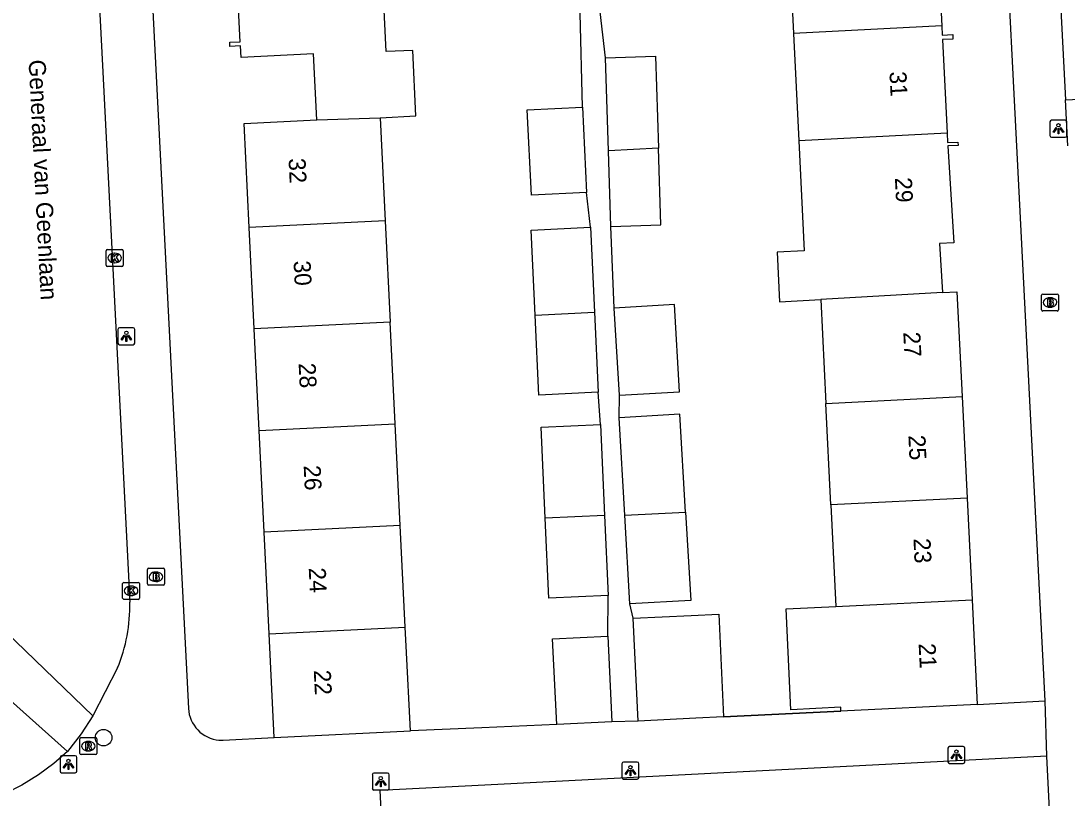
# Model space of a CAD drawing. Extents: x 161084 to 161928, y 385355 to 386522.
# Drawn here: x 161408.5 to 161470.2, y 385913.5 to 385959.4 of the extents above; entities that cross this region are included whole.
import ezdxf

# ---------------------------------------------------------------- set-up
doc = ezdxf.new("R2010")
doc.units = 0
for name, color, linetype in [('IMGEO_Boom', 7, 'Continuous'), ('IMGEO_Brandkraan', 7, 'Continuous'), ('IMGEO_Kolk', 7, 'Continuous'), ('IMGEO_Lichtpunt', 7, 'Continuous'), ('IMGEO_Muur', 7, 'Continuous'), ('IMGEO_Openbare_ruimte_label', 7, 'Continuous'), ('IMGEO_Pand', 7, 'Continuous'), ('IMGEO_Pand_nummerreeks', 7, 'Continuous'), ('IMGEO_Rijbaan_lokaal_open', 7, 'Continuous'), ('IMGEO_Rioolput', 7, 'Continuous'), ('IMGEO_Voetpad_open', 7, 'Continuous')]:
    doc.layers.add(name, color=color, linetype=linetype)

msp = doc.modelspace()

# ---------------------------------------------------------------- linework, layer by layer
at = {"layer": 'IMGEO_Boom'}
msp.add_circle((161413.361, 385917.085), 0.489, dxfattribs=at)
at = {"layer": 'IMGEO_Brandkraan'}
for p, q in [((161468.709, 385942.329), (161468.709, 385943.181)), ((161468.784, 385943.255), (161469.636, 385943.255)), ((161469.71, 385943.181), (161469.71, 385942.329)), ((161469.197, 385943.035), (161469.222, 385943.035)), ((161469.636, 385942.255), (161468.784, 385942.255)), ((161469.22, 385942.475), (161469.195, 385942.475)), ((161416.024, 385927.077), (161416.876, 385927.077)), ((161415.949, 385926.151), (161415.949, 385927.003)), ((161416.437, 385926.857), (161416.462, 385926.857)), ((161416.95, 385927.003), (161416.95, 385926.151)), ((161416.876, 385926.077), (161416.024, 385926.077)), ((161416.46, 385926.297), (161416.435, 385926.297))]:
    msp.add_line(p, q, dxfattribs=at)
for points in [[(161468.709, 385942.329), (161468.709, 385943.181)], [(161468.784, 385943.255), (161469.636, 385943.255)], [(161469.71, 385943.181), (161469.71, 385942.329)], [(161469.057, 385942.955), (161469.057, 385942.555), (161469.27, 385942.555)], [(161469.288, 385942.955), (161469.057, 385942.955)], [(161469.236, 385942.874), (161469.182, 385942.874), (161469.182, 385942.798)], [(161469.182, 385942.798), (161469.235, 385942.798)], [(161469.244, 385942.722), (161469.182, 385942.722), (161469.182, 385942.641)], [(161469.182, 385942.641), (161469.244, 385942.641)], [(161469.636, 385942.255), (161468.784, 385942.255)], [(161416.024, 385927.077), (161416.876, 385927.077)], [(161415.949, 385926.151), (161415.949, 385927.003)], [(161416.297, 385926.777), (161416.297, 385926.377), (161416.51, 385926.377)], [(161416.528, 385926.777), (161416.297, 385926.777)], [(161416.476, 385926.696), (161416.422, 385926.696), (161416.422, 385926.62)], [(161416.422, 385926.62), (161416.475, 385926.62)], [(161416.484, 385926.544), (161416.422, 385926.544), (161416.422, 385926.463)], [(161416.422, 385926.463), (161416.484, 385926.463)], [(161416.95, 385927.003), (161416.95, 385926.151)], [(161416.876, 385926.077), (161416.024, 385926.077)]]:
    msp.add_lwpolyline(points, dxfattribs=at)
for centre, radius, start, end in [((161468.786, 385943.179), 0.0765, 91.55205, 178.44795), ((161468.786, 385943.179), 0.0765, 91.55205, 178.44795), ((161469.634, 385943.179), 0.0765, 1.55205, 88.44795), ((161469.634, 385943.179), 0.0765, 1.55205, 88.44795), ((161469.237, 385942.836), 0.0379, 267.82845, 90.93552), ((161469.245, 385942.681), 0.0404, 269.87594, 90.50774), ((161469.276, 385942.806), 0.251, 268.66757, 293.53466), ((161469.292, 385942.81), 0.145, 59.4692, 91.53667), ((161469.317, 385942.857), 0.0922, 285.51372, 58.15012), ((161469.322, 385942.665), 0.105, 301.31148, 78.98903), ((161468.786, 385942.331), 0.0765, 181.55205, 268.44795), ((161468.786, 385942.331), 0.0765, 181.55205, 268.44795), ((161469.634, 385942.331), 0.0765, 271.55205, 358.44795), ((161469.634, 385942.331), 0.0765, 271.55205, 358.44795), ((161416.026, 385927.001), 0.0765, 91.55205, 178.44795), ((161416.026, 385927.001), 0.0765, 91.55205, 178.44795), ((161416.874, 385927.001), 0.0765, 1.55205, 88.44795), ((161416.874, 385927.001), 0.0765, 1.55205, 88.44795), ((161416.477, 385926.658), 0.0379, 267.82845, 90.93552), ((161416.485, 385926.503), 0.0404, 269.87594, 90.50774), ((161416.532, 385926.632), 0.145, 59.4692, 91.53667), ((161416.557, 385926.679), 0.0922, 285.51372, 58.15012), ((161416.562, 385926.487), 0.105, 301.31148, 78.98903), ((161416.026, 385926.153), 0.0765, 181.55205, 268.44795), ((161416.026, 385926.153), 0.0765, 181.55205, 268.44795), ((161416.516, 385926.628), 0.251, 268.66757, 293.53466), ((161416.874, 385926.153), 0.0765, 271.55205, 358.44795), ((161416.874, 385926.153), 0.0765, 271.55205, 358.44795)]:
    msp.add_arc(centre, radius, start, end, dxfattribs=at)
for centre, major_axis, ratio, start_param, end_param in [((161469.196, 385942.755), (-0.387, 0.002), 0.722429, 4.712389, 7.853982), ((161469.221, 385942.755), (-0.39, 0.002), 0.717154, 1.570796, 4.712389), ((161416.436, 385926.577), (-0.387, 0.002), 0.722429, 4.712389, 7.853982), ((161416.461, 385926.577), (-0.39, 0.002), 0.717154, 1.570796, 4.712389)]:
    msp.add_ellipse(centre, major_axis=major_axis, ratio=ratio, start_param=start_param, end_param=end_param, dxfattribs=at)
at = {"layer": 'IMGEO_Kolk'}
for p, q in [((161413.518, 385944.958), (161413.518, 385945.81)), ((161413.593, 385945.884), (161414.445, 385945.884)), ((161414.006, 385945.664), (161414.031, 385945.664)), ((161414.519, 385945.81), (161414.519, 385944.958)), ((161414.029, 385945.104), (161414.004, 385945.104)), ((161414.445, 385944.884), (161413.593, 385944.884)), ((161414.486, 385925.319), (161414.486, 385926.171)), ((161414.561, 385926.245), (161415.413, 385926.245)), ((161414.974, 385926.025), (161414.999, 385926.025)), ((161415.487, 385926.171), (161415.487, 385925.319)), ((161415.413, 385925.245), (161414.561, 385925.245)), ((161414.997, 385925.465), (161414.972, 385925.465))]:
    msp.add_line(p, q, dxfattribs=at)
for points in [[(161413.518, 385944.958), (161413.518, 385945.81)], [(161413.593, 385945.884), (161414.445, 385945.884)], [(161414.519, 385945.81), (161414.519, 385944.958)], [(161413.839, 385945.584), (161413.962, 385945.584), (161413.962, 385945.433), (161414.092, 385945.584), (161414.256, 385945.584), (161414.11, 385945.433), (161414.263, 385945.184), (161414.111, 385945.184), (161414.026, 385945.348), (161413.962, 385945.281), (161413.962, 385945.184), (161413.839, 385945.184), (161413.839, 385945.584)], [(161414.445, 385944.884), (161413.593, 385944.884)], [(161414.486, 385925.319), (161414.486, 385926.171)], [(161414.561, 385926.245), (161415.413, 385926.245)], [(161414.807, 385925.945), (161414.93, 385925.945), (161414.93, 385925.794), (161415.06, 385925.945), (161415.224, 385925.945), (161415.078, 385925.794), (161415.231, 385925.545), (161415.079, 385925.545), (161414.994, 385925.709), (161414.93, 385925.642), (161414.93, 385925.545), (161414.807, 385925.545), (161414.807, 385925.945)], [(161415.487, 385926.171), (161415.487, 385925.319)], [(161415.413, 385925.245), (161414.561, 385925.245)]]:
    msp.add_lwpolyline(points, dxfattribs=at)
for centre, start, end in [((161413.595, 385945.808), 91.55205, 178.44795), ((161413.595, 385945.808), 91.55205, 178.44795), ((161414.443, 385945.808), 1.55205, 88.44795), ((161414.443, 385945.808), 1.55205, 88.44795), ((161413.595, 385944.96), 181.55205, 268.44795), ((161413.595, 385944.96), 181.55205, 268.44795), ((161414.443, 385944.96), 271.55205, 358.44795), ((161414.443, 385944.96), 271.55205, 358.44795), ((161414.563, 385926.169), 91.55205, 178.44795), ((161414.563, 385926.169), 91.55205, 178.44795), ((161415.411, 385926.169), 1.55205, 88.44795), ((161415.411, 385926.169), 1.55205, 88.44795), ((161414.563, 385925.321), 181.55205, 268.44795), ((161414.563, 385925.321), 181.55205, 268.44795), ((161415.411, 385925.321), 271.55205, 358.44795), ((161415.411, 385925.321), 271.55205, 358.44795)]:
    msp.add_arc(centre, 0.0765, start, end, dxfattribs=at)
for centre, major_axis, ratio, start_param, end_param in [((161414.005, 385945.384), (-0.387, 0.002), 0.722429, 4.712389, 7.853982), ((161414.03, 385945.384), (-0.39, 0.002), 0.717154, 1.570796, 4.712389), ((161414.973, 385925.745), (-0.387, 0.002), 0.722429, 4.712389, 7.853982), ((161414.998, 385925.745), (-0.39, 0.002), 0.717154, 1.570796, 4.712389)]:
    msp.add_ellipse(centre, major_axis=major_axis, ratio=ratio, start_param=start_param, end_param=end_param, dxfattribs=at)
at = {"layer": 'IMGEO_Lichtpunt'}
for p, q in [((161469.204, 385953.412), (161469.204, 385952.605)), ((161469.204, 385953.412), (161469.204, 385952.605)), ((161470.106, 385953.507), (161469.298, 385953.507)), ((161470.106, 385953.507), (161469.298, 385953.507)), ((161470.2, 385952.605), (161470.2, 385953.412)), ((161470.2, 385952.605), (161470.2, 385953.412)), ((161469.298, 385952.511), (161470.106, 385952.511)), ((161469.298, 385952.511), (161470.106, 385952.511)), ((161415.11, 385941.264), (161414.302, 385941.264)), ((161415.11, 385941.264), (161414.302, 385941.264)), ((161414.208, 385941.169), (161414.208, 385940.362)), ((161414.208, 385941.169), (161414.208, 385940.362)), ((161415.204, 385940.362), (161415.204, 385941.169)), ((161415.204, 385940.362), (161415.204, 385941.169)), ((161414.302, 385940.268), (161415.11, 385940.268)), ((161414.302, 385940.268), (161415.11, 385940.268)), ((161411.694, 385916.012), (161410.886, 385916.012)), ((161411.694, 385916.012), (161410.886, 385916.012)), ((161463.185, 385916.467), (161463.185, 385915.66)), ((161463.185, 385916.467), (161463.185, 385915.66)), ((161464.087, 385916.562), (161463.279, 385916.562)), ((161464.087, 385916.562), (161463.279, 385916.562)), ((161464.181, 385915.66), (161464.181, 385916.467)), ((161464.181, 385915.66), (161464.181, 385916.467)), ((161410.792, 385915.917), (161410.792, 385915.11)), ((161410.792, 385915.917), (161410.792, 385915.11)), ((161411.788, 385915.11), (161411.788, 385915.917)), ((161411.788, 385915.11), (161411.788, 385915.917)), ((161443.951, 385915.545), (161443.951, 385914.738)), ((161443.951, 385915.545), (161443.951, 385914.738)), ((161444.853, 385915.64), (161444.045, 385915.64)), ((161444.853, 385915.64), (161444.045, 385915.64)), ((161444.947, 385914.738), (161444.947, 385915.545)), ((161444.947, 385914.738), (161444.947, 385915.545)), ((161463.279, 385915.566), (161464.087, 385915.566)), ((161463.279, 385915.566), (161464.087, 385915.566)), ((161410.886, 385915.016), (161411.694, 385915.016)), ((161410.886, 385915.016), (161411.694, 385915.016)), ((161429.22, 385914.899), (161429.22, 385914.092)), ((161429.22, 385914.899), (161429.22, 385914.092)), ((161430.122, 385914.994), (161429.314, 385914.994)), ((161430.122, 385914.994), (161429.314, 385914.994)), ((161430.216, 385914.092), (161430.216, 385914.899)), ((161430.216, 385914.092), (161430.216, 385914.899)), ((161444.045, 385914.644), (161444.853, 385914.644)), ((161444.045, 385914.644), (161444.853, 385914.644)), ((161429.314, 385913.998), (161430.122, 385913.998)), ((161429.314, 385913.998), (161430.122, 385913.998))]:
    msp.add_line(p, q, dxfattribs=at)
for points in [[(161469.578, 385953.076), (161469.617, 385953.048), (161469.429, 385952.786), (161469.391, 385952.813), (161469.578, 385953.076)], [(161469.68, 385953.028), (161469.727, 385953.028), (161469.727, 385952.706), (161469.68, 385952.706), (161469.68, 385953.028)], [(161469.79, 385953.048), (161469.828, 385953.075), (161470.015, 385952.813), (161469.976, 385952.785), (161469.79, 385953.048)], [(161414.582, 385940.833), (161414.621, 385940.805), (161414.433, 385940.543), (161414.395, 385940.57), (161414.582, 385940.833)], [(161414.684, 385940.785), (161414.731, 385940.785), (161414.731, 385940.463), (161414.684, 385940.463), (161414.684, 385940.785)], [(161414.794, 385940.805), (161414.832, 385940.832), (161415.019, 385940.57), (161414.98, 385940.542), (161414.794, 385940.805)], [(161463.559, 385916.131), (161463.598, 385916.103), (161463.41, 385915.841), (161463.372, 385915.868), (161463.559, 385916.131)], [(161463.661, 385916.083), (161463.708, 385916.083), (161463.708, 385915.761), (161463.661, 385915.761), (161463.661, 385916.083)], [(161463.771, 385916.103), (161463.809, 385916.13), (161463.996, 385915.868), (161463.957, 385915.84), (161463.771, 385916.103)], [(161411.166, 385915.581), (161411.205, 385915.553), (161411.017, 385915.291), (161410.979, 385915.318), (161411.166, 385915.581)], [(161411.268, 385915.533), (161411.315, 385915.533), (161411.315, 385915.211), (161411.268, 385915.211), (161411.268, 385915.533)], [(161411.378, 385915.553), (161411.416, 385915.58), (161411.603, 385915.318), (161411.564, 385915.29), (161411.378, 385915.553)], [(161444.325, 385915.209), (161444.364, 385915.181), (161444.176, 385914.919), (161444.138, 385914.946), (161444.325, 385915.209)], [(161444.427, 385915.161), (161444.474, 385915.161), (161444.474, 385914.839), (161444.427, 385914.839), (161444.427, 385915.161)], [(161444.537, 385915.181), (161444.575, 385915.208), (161444.762, 385914.946), (161444.723, 385914.918), (161444.537, 385915.181)], [(161429.594, 385914.563), (161429.633, 385914.535), (161429.445, 385914.273), (161429.407, 385914.3), (161429.594, 385914.563)], [(161429.696, 385914.515), (161429.743, 385914.515), (161429.743, 385914.193), (161429.696, 385914.193), (161429.696, 385914.515)], [(161429.806, 385914.535), (161429.844, 385914.562), (161430.031, 385914.3), (161429.992, 385914.272), (161429.806, 385914.535)]]:
    msp.add_lwpolyline(points, dxfattribs=at)
for centre in [(161469.703, 385953.21), (161414.707, 385940.967), (161463.684, 385916.265), (161411.291, 385915.715), (161444.45, 385915.343), (161429.719, 385914.697)]:
    msp.add_circle(centre, 0.0994, dxfattribs=at)
for centre, start, end in [((161469.298, 385953.412), 90, 180), ((161469.298, 385953.412), 90, 180), ((161470.106, 385953.412), 0, 90), ((161470.106, 385953.412), 0, 90), ((161469.298, 385952.605), 180, 270), ((161469.298, 385952.605), 180, 270), ((161470.106, 385952.605), 270, 0), ((161470.106, 385952.605), 270, 360), ((161414.302, 385941.169), 90, 180), ((161414.302, 385941.169), 90, 180), ((161415.11, 385941.169), 0, 90), ((161415.11, 385941.169), 0, 90), ((161414.302, 385940.362), 180, 270), ((161414.302, 385940.362), 180, 270), ((161415.11, 385940.362), 270, 0), ((161415.11, 385940.362), 270, 360), ((161410.886, 385915.917), 90, 180), ((161410.886, 385915.917), 90, 180), ((161411.694, 385915.917), 0, 90), ((161411.694, 385915.917), 0, 90), ((161463.279, 385916.467), 90, 180), ((161463.279, 385916.467), 90, 180), ((161464.087, 385916.467), 0, 90), ((161464.087, 385916.467), 0, 90), ((161444.045, 385915.545), 90, 180), ((161444.045, 385915.545), 90, 180), ((161444.853, 385915.545), 0, 90), ((161444.853, 385915.545), 0, 90), ((161463.279, 385915.66), 180, 270), ((161463.279, 385915.66), 180, 270), ((161464.087, 385915.66), 270, 0), ((161464.087, 385915.66), 270, 360), ((161410.886, 385915.11), 180, 270), ((161410.886, 385915.11), 180, 270), ((161411.694, 385915.11), 270, 0), ((161411.694, 385915.11), 270, 360), ((161429.314, 385914.899), 90, 180), ((161429.314, 385914.899), 90, 180), ((161430.122, 385914.899), 0, 90), ((161430.122, 385914.899), 0, 90), ((161444.045, 385914.738), 180, 270), ((161444.045, 385914.738), 180, 270), ((161444.853, 385914.738), 270, 0), ((161444.853, 385914.738), 270, 360), ((161429.314, 385914.092), 180, 270), ((161429.314, 385914.092), 180, 270), ((161430.122, 385914.092), 270, 0), ((161430.122, 385914.092), 270, 360)]:
    msp.add_arc(centre, 0.0946, start, end, dxfattribs=at)
at = {"layer": 'IMGEO_Muur'}
for points in [[(161449.948, 385918.309), (161456.873, 385918.643)], [(161440.097, 385917.865), (161435.675, 385917.671)], [(161435.675, 385917.671), (161431.468, 385917.486)]]:
    msp.add_lwpolyline(points, dxfattribs=at)
at = {"layer": 'IMGEO_Pand'}
for points in [[(161462.514, 385965.409), (161462.544, 385964.801), (161463.153, 385964.831), (161463.165, 385964.591), (161462.547, 385964.56), (161462.817, 385959.075)], [(161453.757, 385964.955), (161454.069, 385958.622)], [(161425.937, 385953.528), (161425.745, 385957.419), (161421.473, 385957.208), (161421.439, 385957.896), (161420.816, 385957.865), (161420.804, 385958.11), (161421.415, 385958.14), (161421.144, 385963.626)], [(161429.681, 385953.656), (161431.792, 385953.761), (161431.601, 385957.62), (161430.045, 385957.571), (161429.724, 385964.062)], [(161462.817, 385959.075), (161454.069, 385958.622)], [(161454.069, 385958.622), (161454.38, 385952.29)], [(161462.817, 385959.075), (161462.844, 385958.532), (161463.467, 385958.563), (161463.48, 385958.299), (161462.861, 385958.269), (161463.133, 385952.744)], [(161442.975, 385957.188), (161445.932, 385957.281), (161446.103, 385951.861)], [(161443.148, 385951.707), (161442.975, 385957.188)], [(161441.86, 385949.243), (161438.602, 385949.087), (161438.361, 385954.131), (161441.619, 385954.287)], [(161441.619, 385954.287), (161441.86, 385949.243)], [(161425.937, 385953.528), (161429.681, 385953.656)], [(161429.681, 385953.656), (161429.981, 385947.583)], [(161421.951, 385947.187), (161421.648, 385953.316), (161425.937, 385953.528)], [(161463.133, 385952.744), (161454.38, 385952.29)], [(161463.133, 385952.744), (161463.16, 385952.19), (161463.772, 385952.22), (161463.782, 385952.019), (161463.18, 385951.989), (161463.536, 385946.272), (161462.687, 385946.227), (161462.857, 385943.338)], [(161446.103, 385951.861), (161443.148, 385951.707)], [(161443.289, 385947.244), (161446.246, 385947.338), (161446.103, 385951.861)], [(161454.38, 385952.29), (161454.699, 385945.795), (161453.112, 385945.717), (161453.236, 385942.788), (161455.678, 385942.939)], [(161443.289, 385947.244), (161443.148, 385951.707)], [(161429.981, 385947.583), (161421.951, 385947.187)], [(161429.981, 385947.583), (161430.277, 385941.59)], [(161422.247, 385941.194), (161421.951, 385947.187)], [(161438.83, 385942.012), (161438.597, 385947.031), (161442.097, 385947.193)], [(161442.097, 385947.193), (161442.33, 385942.184)], [(161462.857, 385943.338), (161455.678, 385942.939)], [(161462.857, 385943.338), (161463.716, 385943.38), (161464.02, 385937.202)], [(161443.795, 385937.285), (161447.353, 385937.493), (161447.053, 385942.629), (161443.495, 385942.422)], [(161455.678, 385942.939), (161455.98, 385936.805)], [(161438.83, 385942.012), (161442.33, 385942.184)], [(161442.549, 385937.46), (161439.049, 385937.297), (161438.83, 385942.012)], [(161442.33, 385942.184), (161442.549, 385937.46)], [(161443.795, 385937.285), (161443.495, 385942.422)], [(161430.277, 385941.59), (161422.247, 385941.194)], [(161430.573, 385935.598), (161430.277, 385941.59)], [(161422.543, 385935.202), (161422.247, 385941.194)], [(161455.98, 385936.805), (161464.02, 385937.202)], [(161464.02, 385937.202), (161464.314, 385931.21)], [(161456.275, 385930.814), (161455.98, 385936.805)], [(161447.707, 385930.392), (161447.372, 385936.166), (161443.785, 385935.958)], [(161444.118, 385930.215), (161443.785, 385935.958)], [(161422.543, 385935.202), (161430.573, 385935.598)], [(161422.838, 385929.209), (161422.543, 385935.202)], [(161430.869, 385929.605), (161430.573, 385935.598)], [(161439.422, 385930.027), (161439.173, 385935.398), (161442.673, 385935.561)], [(161442.673, 385935.561), (161442.922, 385930.199)], [(161464.314, 385931.21), (161456.275, 385930.814)], [(161456.275, 385930.814), (161456.57, 385924.82)], [(161464.314, 385931.21), (161464.609, 385925.217)], [(161442.922, 385930.199), (161439.422, 385930.027)], [(161442.922, 385930.199), (161443.141, 385925.475)], [(161444.118, 385930.215), (161447.707, 385930.392)], [(161444.422, 385924.973), (161444.118, 385930.215)], [(161447.707, 385930.392), (161448.009, 385925.181), (161444.422, 385924.973)], [(161430.869, 385929.605), (161422.838, 385929.209)], [(161431.165, 385923.612), (161430.869, 385929.605)], [(161443.141, 385925.475), (161439.641, 385925.312), (161439.422, 385930.027)], [(161423.134, 385923.216), (161422.838, 385929.209)], [(161456.57, 385924.82), (161464.609, 385925.217)], [(161464.609, 385925.217), (161464.913, 385919.038)], [(161456.873, 385918.643), (161456.862, 385918.875), (161453.92, 385918.73), (161453.628, 385924.676), (161456.57, 385924.82)], [(161444.614, 385924.132), (161448.023, 385924.293), (161449.658, 385924.37), (161449.948, 385918.309)], [(161444.904, 385918.068), (161444.614, 385924.132)], [(161423.134, 385923.216), (161431.165, 385923.612)], [(161431.468, 385917.486), (161431.221, 385922.48), (161431.165, 385923.612)], [(161423.437, 385917.089), (161423.134, 385923.216)], [(161440.097, 385917.865), (161439.856, 385922.909), (161443.114, 385923.065)], [(161443.114, 385923.065), (161443.355, 385918.021)], [(161464.913, 385919.038), (161456.873, 385918.643)], [(161443.355, 385918.021), (161440.097, 385917.865)], [(161449.948, 385918.309), (161448.313, 385918.231), (161444.904, 385918.068)], [(161423.437, 385917.089), (161431.468, 385917.486)]]:
    msp.add_lwpolyline(points, dxfattribs=at)
at = {"layer": 'IMGEO_Rijbaan_lokaal_open'}
for points in [[(161410.629, 386009.305), (161411.335, 385994.667), (161413.296, 385956.735), (161413.505, 385952.859), (161414.906, 385925.074)], [(161467.737, 386000.824), (161467.781, 386000), (161470.11, 385954.706)], [(161470.11, 385954.706), (161477.129, 385955.051)], [(161470.249, 385951.99), (161470.11, 385954.706)], [(161407.607, 385923.314), (161412.736, 385918.37)], [(161411.224, 385916.273), (161405.988, 385920.958)], [(161414.183, 385921.198), (161412.736, 385918.37)], [(161412.736, 385918.37), (161412.036, 385917.311), (161411.224, 385916.273)], [(161411.224, 385916.273), (161410.433, 385915.569), (161409.519, 385914.886), (161408.548, 385914.288), (161407.528, 385913.779), (161406.465, 385913.364), (161405.37, 385913.044), (161404.251, 385912.824), (161403.117, 385912.705), (161398.69, 385912.468)], [(161469.013, 385915.99), (161435.86, 385914.286), (161429.657, 385913.967), (161429.951, 385908.251)], [(161469.278, 385910.865), (161469.013, 385915.99)]]:
    msp.add_lwpolyline(points, dxfattribs=at)
msp.add_arc((161405.5, 385924.823), 9.41, 337.34001, 1.5278, dxfattribs=at)
at = {"layer": 'IMGEO_Rioolput'}
for p, q in [((161411.958, 385916.16), (161411.958, 385917.012)), ((161412.033, 385917.086), (161412.885, 385917.086)), ((161412.446, 385916.866), (161412.471, 385916.866)), ((161412.959, 385917.012), (161412.959, 385916.16)), ((161412.885, 385916.086), (161412.033, 385916.086)), ((161412.469, 385916.306), (161412.444, 385916.306))]:
    msp.add_line(p, q, dxfattribs=at)
for points in [[(161411.958, 385916.16), (161411.958, 385917.012)], [(161412.033, 385917.086), (161412.885, 385917.086)], [(161412.547, 385916.784), (161412.295, 385916.786), (161412.295, 385916.386)], [(161412.473, 385916.705), (161412.419, 385916.705), (161412.419, 385916.624)], [(161412.419, 385916.624), (161412.471, 385916.624)], [(161412.959, 385917.012), (161412.959, 385916.16)], [(161412.885, 385916.086), (161412.033, 385916.086)], [(161412.295, 385916.386), (161412.419, 385916.386), (161412.419, 385916.548), (161412.43, 385916.548)], [(161412.477, 385916.519), (161412.548, 385916.386), (161412.688, 385916.386), (161412.623, 385916.512)]]:
    msp.add_lwpolyline(points, dxfattribs=at)
for centre, radius, start, end in [((161412.035, 385917.01), 0.0765, 91.55205, 178.44795), ((161412.035, 385917.01), 0.0765, 91.55205, 178.44795), ((161412.455, 385916.813), 0.19, 274.7715, 282.96867), ((161412.479, 385916.609), 0.0964, 77.00612, 93.18647), ((161412.493, 385916.666), 0.0378, 276.66336, 79.67722), ((161412.546, 385916.674), 0.109, 350.36119, 89.41601), ((161412.544, 385916.674), 0.112, 277.58423, 350.98172), ((161412.883, 385917.01), 0.0765, 1.55205, 88.44795), ((161412.883, 385917.01), 0.0765, 1.55205, 88.44795), ((161412.035, 385916.162), 0.0765, 181.55205, 268.44795), ((161412.035, 385916.162), 0.0765, 181.55205, 268.44795), ((161412.429, 385916.495), 0.0533, 26.02933, 88.69889), ((161412.528, 385916.459), 0.108, 29.51342, 73.79051), ((161412.883, 385916.162), 0.0765, 271.55205, 358.44795), ((161412.883, 385916.162), 0.0765, 271.55205, 358.44795)]:
    msp.add_arc(centre, radius, start, end, dxfattribs=at)
for centre, major_axis, ratio, start_param, end_param in [((161412.445, 385916.586), (-0.387, 0.002), 0.722429, 4.712389, 7.853982), ((161412.47, 385916.586), (-0.39, 0.002), 0.717154, 1.570796, 4.712389)]:
    msp.add_ellipse(centre, major_axis=major_axis, ratio=ratio, start_param=start_param, end_param=end_param, dxfattribs=at)
at = {"layer": 'IMGEO_Voetpad_open'}
for points in [[(161468.916, 385919.263), (161464.934, 385997.415)], [(161414.479, 385994.976), (161418.37, 385918.809), (161418.387, 385918.633), (161418.42, 385918.459), (161418.468, 385918.289), (161418.531, 385918.124), (161418.608, 385917.965), (161418.7, 385917.814), (161418.804, 385917.671), (161418.921, 385917.538), (161419.049, 385917.417), (161419.188, 385917.307), (161419.336, 385917.21), (161419.492, 385917.127), (161419.655, 385917.058), (161419.823, 385917.004), (161419.996, 385916.965), (161420.171, 385916.941), (161420.347, 385916.933), (161420.422, 385916.935), (161423.437, 385917.089)], [(161441.619, 385954.287), (161441.486, 385959.821)], [(161442.975, 385957.188), (161442.666, 385959.909)], [(161442.097, 385947.193), (161441.86, 385949.243)], [(161443.495, 385942.422), (161443.289, 385947.244)], [(161442.673, 385935.561), (161442.549, 385937.46)], [(161443.785, 385935.958), (161443.795, 385937.285)], [(161443.114, 385923.065), (161443.141, 385925.475)], [(161444.614, 385924.132), (161444.422, 385924.973)], [(161464.913, 385919.038), (161468.916, 385919.263)], [(161469.013, 385915.99), (161468.916, 385919.263)], [(161456.873, 385918.643), (161449.948, 385918.309)], [(161440.097, 385917.865), (161435.675, 385917.671), (161431.468, 385917.486)], [(161444.904, 385918.068), (161443.355, 385918.021)]]:
    msp.add_lwpolyline(points, dxfattribs=at)

# ---------------------------------------------------------------- texts
at = {"layer": 'IMGEO_Openbare_ruimte_label'}
msp.add_text('Generaal van Geenlaan', height=1, rotation=272.92247, dxfattribs=at).set_placement((161408.936, 385957.058))
at = {"layer": 'IMGEO_Pand_nummerreeks'}
for s, rotation, p in [('31', 272.9678, (161459.729, 385956.366)), ('32', 272.82714, (161424.274, 385951.25)), ('29', 272.9678, (161460.053, 385950.112)), ('30', 272.82714, (161424.572, 385945.206)), ('27', 272.81521, (161460.549, 385941.002)), ('28', 272.82714, (161424.87, 385939.168)), ('25', 272.81521, (161460.848, 385934.916)), ('26', 272.82714, (161425.168, 385933.134)), ('23', 272.81521, (161461.148, 385928.831)), ('24', 272.82714, (161425.466, 385927.096)), ('21', 272.81301, (161461.453, 385922.632)), ('22', 272.82714, (161425.764, 385921.061))]:
    msp.add_text(s, height=1, rotation=rotation, dxfattribs=at).set_placement(p)

doc.saveas('drawing.dxf')
